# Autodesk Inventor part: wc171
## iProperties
Shininess: 64.0
Length Units: 11272
Angle Units: 11279
Time Units: 11290
Mass Units: 11286
Length Display Precision: 3
Angle Display Precision: 2
Compacted: True
Part Number: wc171
Document SubType Name: Modeling
Created: 2004-08
Designer: John Blackburn
Manufacturer: Standard
Standards Organization: Custom
Material: Phenolic
Density: 0.0
Volumn: 0.0
Area: 0.0
PropertySet Name: Model Information
Control State: 0
Master: False
Checked Out: False
Author: John Blackburn
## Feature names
1. Base1
